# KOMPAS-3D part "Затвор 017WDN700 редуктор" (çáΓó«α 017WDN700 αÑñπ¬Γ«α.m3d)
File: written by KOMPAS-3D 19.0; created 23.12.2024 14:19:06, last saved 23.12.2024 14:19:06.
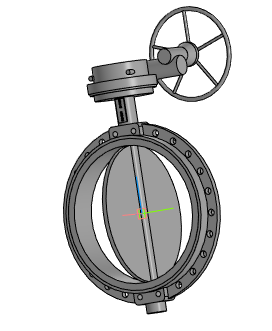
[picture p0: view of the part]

Document properties: Автор: Евгений; Полное имя файла: ..\Затвор 017WDN700 редуктор.a3d

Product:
- Part/product: Затвор 017WDN700 редуктор
    Масса: 415.881

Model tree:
1. Операция без истории:1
